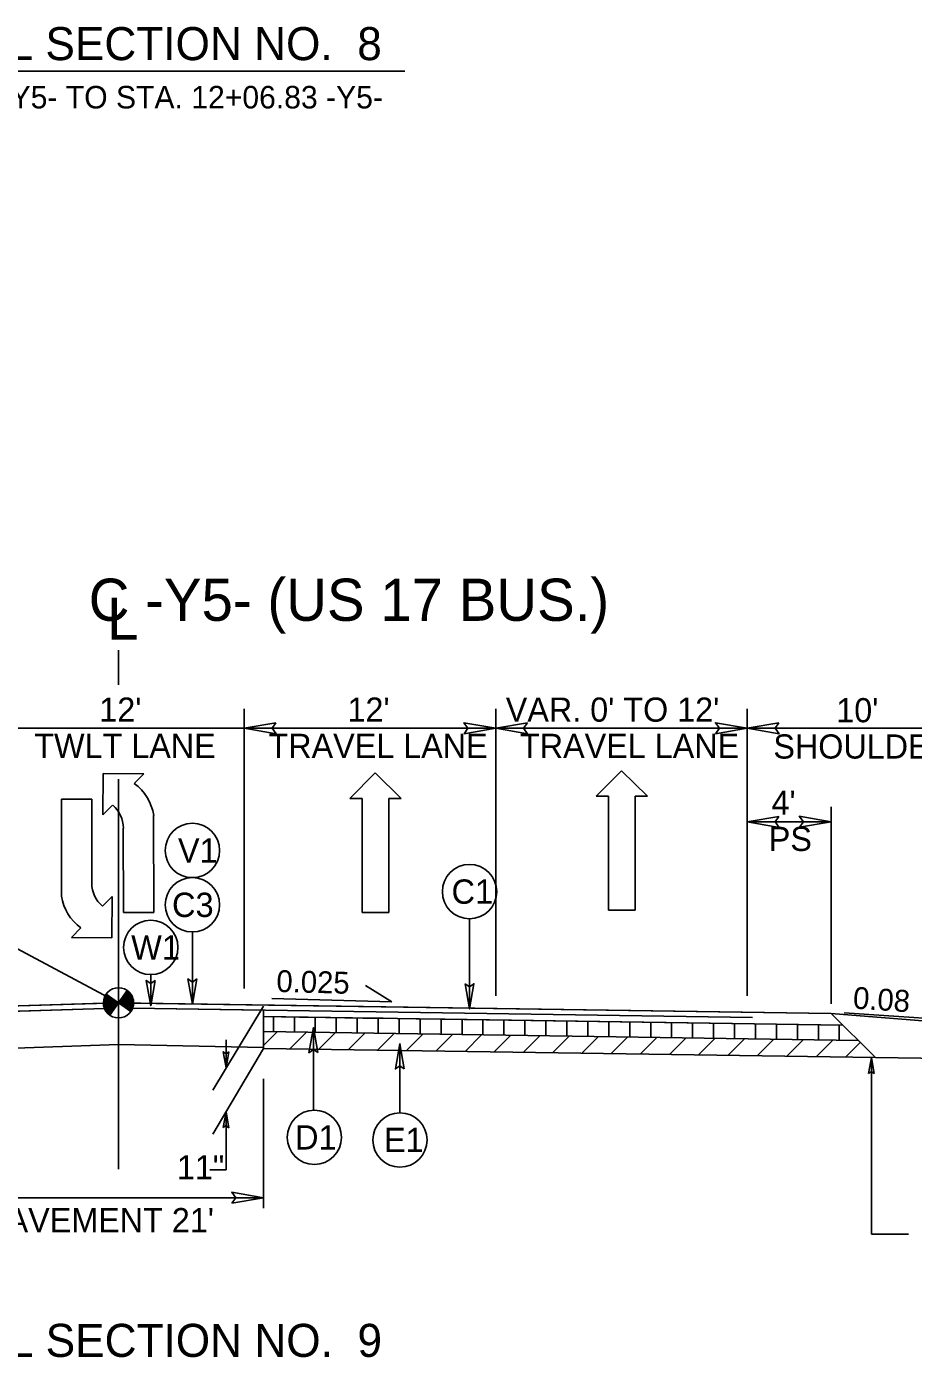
# Model space of a CAD drawing. Extents: x 2176156 to 2177167, y 76401 to 76644.
# Drawn here: x 2176792.8 to 2176835.1, y 76511.9 to 76575.4 of the extents above; entities that cross this region are included whole.
import ezdxf

# ---------------------------------------------------------------- set-up
doc = ezdxf.new("R2010")
doc.units = 0
for name, color, linetype in [('Exist Building', 7, 'Continuous'), ('Exist Building Metal Canopy', 7, 'Continuous'), ('Exist Roads Change in Surface', 7, 'Continuous'), ('Exist Roads Curbs', 7, 'Continuous'), ('Exist Roads EOP Other', 7, 'Continuous'), ('Exist Roads Soil', 7, 'Continuous'), ('Exist Structure Minor Culvert Topo', 7, 'Continuous'), ('Exist Structure Minor Drop Inlet', 7, 'Continuous'), ('Exist Utilities Other Pole CELL', 7, 'Continuous'), ('Exist Vegetation Tree CELL', 7, 'Continuous'), ('Exist Vegetation Woods Line', 7, 'Continuous'), ('Model Boundary Lines Text', 7, 'Continuous'), ('Old_Level_1', 7, 'Continuous'), ('Old_Level_3', 7, 'Continuous'), ('Prop North Arrow NAD83 for Plan Sheets CELL', 7, 'Continuous'), ('Sheet Plan CELL', 7, 'Continuous')]:
    doc.layers.add(name, color=color, linetype=linetype)

msp = doc.modelspace()

# ---------------------------------------------------------------- linework, layer by layer
at = {"layer": 'Exist Building'}
for p, q in [((2176804.065, 76526.664), (2176804.065, 76528.486)), ((2176848.249, 76526.006), (2176804.065, 76526.664))]:
    msp.add_line(p, q, dxfattribs=at)
at = {"layer": 'Exist Roads Change in Surface'}
for p, q in [((2176797.558, 76529.431), (2176797.146, 76528.839)), ((2176797.146, 76528.839), (2176796.554, 76529.251)), ((2176796.734, 76528.247), (2176797.146, 76528.839)), ((2176797.738, 76528.428), (2176797.146, 76528.839)), ((2176797.146, 76528.839), (2176797.738, 76528.428))]:
    msp.add_line(p, q, dxfattribs=at)
for points in [[(2176797.531, 76529.392), (2176797.743, 76529.245)], [(2176797.539, 76529.404), (2176797.715, 76529.282)], [(2176797.548, 76529.416), (2176797.682, 76529.323)], [(2176797.556, 76529.428), (2176797.62, 76529.383)], [(2176796.425, 76528.858), (2176796.92, 76528.514)], [(2176796.425, 76528.841), (2176796.912, 76528.502)], [(2176796.426, 76528.876), (2176796.928, 76528.526)], [(2176796.426, 76528.823), (2176796.903, 76528.49)], [(2176796.426, 76528.805), (2176796.895, 76528.479)], [(2176796.427, 76528.892), (2176796.936, 76528.538)], [(2176796.427, 76528.787), (2176796.887, 76528.467)], [(2176796.429, 76528.908), (2176796.945, 76528.55)], [(2176796.429, 76528.768), (2176796.879, 76528.455)], [(2176796.431, 76528.925), (2176796.953, 76528.561)], [(2176796.432, 76528.941), (2176796.961, 76528.573)], [(2176796.435, 76528.957), (2176796.969, 76528.585)], [(2176796.438, 76528.972), (2176796.977, 76528.597)], [(2176796.441, 76528.988), (2176796.986, 76528.609)], [(2176796.444, 76529.003), (2176796.994, 76528.621)], [(2176796.447, 76529.019), (2176797.002, 76528.632)], [(2176796.452, 76529.033), (2176797.01, 76528.644)], [(2176796.456, 76529.048), (2176797.019, 76528.656)], [(2176796.46, 76529.062), (2176797.027, 76528.668)], [(2176796.466, 76529.076), (2176797.035, 76528.68)], [(2176796.47, 76529.091), (2176797.043, 76528.692)], [(2176796.476, 76529.104), (2176797.052, 76528.703)], [(2176796.481, 76529.118), (2176797.06, 76528.715)], [(2176796.487, 76529.132), (2176797.068, 76528.727)], [(2176796.492, 76529.145), (2176797.076, 76528.739)], [(2176796.499, 76529.158), (2176797.084, 76528.751)], [(2176796.506, 76529.171), (2176797.093, 76528.763)], [(2176796.513, 76529.183), (2176797.101, 76528.774)], [(2176796.52, 76529.196), (2176797.109, 76528.786)], [(2176796.527, 76529.209), (2176797.117, 76528.798)], [(2176796.535, 76529.221), (2176797.126, 76528.81)], [(2176796.542, 76529.234), (2176797.134, 76528.822)], [(2176796.55, 76529.245), (2176796.55, 76529.245), (2176797.142, 76528.834)], [(2176797.152, 76528.848), (2176797.744, 76528.436), (2176797.744, 76528.436)], [(2176797.16, 76528.86), (2176797.752, 76528.448)], [(2176797.169, 76528.872), (2176797.759, 76528.461)], [(2176797.177, 76528.884), (2176797.767, 76528.473)], [(2176797.185, 76528.895), (2176797.774, 76528.486)], [(2176797.193, 76528.907), (2176797.781, 76528.498)], [(2176797.202, 76528.919), (2176797.788, 76528.511)], [(2176797.21, 76528.931), (2176797.794, 76528.525)], [(2176797.218, 76528.943), (2176797.801, 76528.537)], [(2176797.226, 76528.955), (2176797.806, 76528.551)], [(2176797.235, 76528.966), (2176797.812, 76528.565)], [(2176797.243, 76528.978), (2176797.817, 76528.578)], [(2176797.251, 76528.99), (2176797.823, 76528.592)], [(2176797.259, 76529.002), (2176797.827, 76528.607)], [(2176797.267, 76529.014), (2176797.833, 76528.62)], [(2176797.276, 76529.026), (2176797.837, 76528.635)], [(2176797.284, 76529.037), (2176797.841, 76528.649)], [(2176797.292, 76529.049), (2176797.846, 76528.664)], [(2176797.3, 76529.061), (2176797.849, 76528.68)], [(2176797.309, 76529.073), (2176797.852, 76528.695)], [(2176797.317, 76529.085), (2176797.855, 76528.71)], [(2176797.325, 76529.097), (2176797.858, 76528.726)], [(2176797.333, 76529.108), (2176797.861, 76528.741)], [(2176797.342, 76529.12), (2176797.862, 76528.758)], [(2176797.35, 76529.132), (2176797.864, 76528.774)], [(2176797.358, 76529.144), (2176797.866, 76528.791)], [(2176797.366, 76529.156), (2176797.866, 76528.808)], [(2176797.375, 76529.168), (2176797.866, 76528.825)], [(2176797.383, 76529.179), (2176797.867, 76528.843)], [(2176797.391, 76529.191), (2176797.867, 76528.86)], [(2176797.399, 76529.203), (2176797.866, 76528.878)], [(2176797.407, 76529.215), (2176797.865, 76528.897)], [(2176797.416, 76529.227), (2176797.863, 76528.916)], [(2176797.424, 76529.239), (2176797.86, 76528.935)], [(2176797.432, 76529.25), (2176797.858, 76528.954)], [(2176797.44, 76529.262), (2176797.855, 76528.974)], [(2176797.449, 76529.274), (2176797.85, 76528.995)], [(2176797.457, 76529.286), (2176797.845, 76529.016)], [(2176797.465, 76529.298), (2176797.839, 76529.038)], [(2176797.473, 76529.31), (2176797.832, 76529.06)], [(2176797.482, 76529.321), (2176797.825, 76529.083)], [(2176797.49, 76529.333), (2176797.816, 76529.106)], [(2176797.498, 76529.345), (2176797.806, 76529.131)], [(2176797.506, 76529.357), (2176797.793, 76529.157)], [(2176797.515, 76529.369), (2176797.779, 76529.185)], [(2176797.523, 76529.381), (2176797.762, 76529.214)], [(2176796.431, 76528.749), (2176796.87, 76528.443)], [(2176796.434, 76528.73), (2176796.862, 76528.431)], [(2176796.437, 76528.71), (2176796.854, 76528.419)], [(2176796.441, 76528.689), (2176796.846, 76528.408)], [(2176796.446, 76528.668), (2176796.837, 76528.396)], [(2176796.452, 76528.647), (2176796.829, 76528.384)], [(2176796.458, 76528.625), (2176796.821, 76528.372)], [(2176796.466, 76528.602), (2176796.813, 76528.36)], [(2176796.474, 76528.578), (2176796.804, 76528.348)], [(2176796.485, 76528.553), (2176796.796, 76528.337)], [(2176796.496, 76528.528), (2176796.788, 76528.325)], [(2176796.509, 76528.501), (2176796.78, 76528.313)], [(2176796.526, 76528.472), (2176796.772, 76528.301)], [(2176796.545, 76528.441), (2176796.763, 76528.289)], [(2176796.57, 76528.406), (2176796.755, 76528.277)], [(2176796.602, 76528.366), (2176796.747, 76528.266)], [(2176796.654, 76528.312), (2176796.739, 76528.254)]]:
    msp.add_lwpolyline(points, dxfattribs=at)
msp.add_circle((2176797.146, 76528.84), 0.721, dxfattribs=at)
for start, end in [(325.1751, 55.1751), (145.1751, 235.1751)]:
    msp.add_arc((2176797.146, 76528.84), 0.721, start, end, dxfattribs=at)
at = {"layer": 'Exist Roads Curbs'}
for p, q in [((2176797.146, 76528.839), (2176763.146, 76527.778)), ((2176797.146, 76528.839), (2176831.146, 76528.334)), ((2176796.478, 76528.568), (2176762.886, 76527.52)), ((2176797.818, 76528.579), (2176827.401, 76528.139))]:
    msp.add_line(p, q, dxfattribs=at)
at = {"layer": 'Exist Roads EOP Other'}
for p, q in [((2176796.426, 76528.816), (2176763.146, 76527.778)), ((2176796.426, 76528.805), (2176796.426, 76528.805)), ((2176796.427, 76528.787), (2176796.427, 76528.787)), ((2176797.865, 76528.791), (2176797.866, 76528.791)), ((2176831.146, 76528.334), (2176797.867, 76528.828)), ((2176796.434, 76528.729), (2176796.434, 76528.73)), ((2176796.437, 76528.71), (2176796.437, 76528.71)), ((2176796.441, 76528.689), (2176796.441, 76528.689)), ((2176796.446, 76528.668), (2176796.446, 76528.668)), ((2176796.458, 76528.625), (2176796.458, 76528.625)), ((2176796.466, 76528.602), (2176796.466, 76528.602)), ((2176797.833, 76528.62), (2176797.833, 76528.62)), ((2176797.841, 76528.649), (2176797.841, 76528.649)), ((2176797.845, 76528.664), (2176797.846, 76528.664)), ((2176797.86, 76528.742), (2176797.861, 76528.741)), ((2176831.146, 76528.334), (2176837.181, 76527.851)), ((2176831.708, 76527.774), (2176831.146, 76528.334)), ((2176812.737, 76528.055), (2176831.708, 76527.774))]:
    msp.add_line(p, q, dxfattribs=at)
for points in [[(2176796.426, 76528.805), (2176796.426, 76528.805)], [(2176796.427, 76528.787), (2176796.427, 76528.787)], [(2176797.866, 76528.791), (2176797.865, 76528.791)], [(2176773.445, 76527.464), (2176774.959, 76527.487), (2176776.433, 76527.509), (2176777.013, 76527.517), (2176777.705, 76527.527), (2176778.76, 76527.543), (2176780.289, 76527.566), (2176780.289, 76528.063), (2176796.478, 76528.568)], [(2176796.434, 76528.73), (2176796.434, 76528.73)], [(2176796.437, 76528.71), (2176796.437, 76528.71)], [(2176796.441, 76528.689), (2176796.441, 76528.69)], [(2176796.446, 76528.668), (2176796.446, 76528.669)], [(2176796.458, 76528.625), (2176796.458, 76528.625)], [(2176796.466, 76528.602), (2176796.466, 76528.602)], [(2176797.818, 76528.579), (2176804.065, 76528.486), (2176804.065, 76528.186), (2176805.775, 76528.16), (2176807.023, 76528.142), (2176807.947, 76528.128), (2176808.797, 76528.115), (2176809.773, 76528.101), (2176810.454, 76528.091), (2176811.35, 76528.077), (2176812.737, 76528.055)], [(2176797.833, 76528.62), (2176797.833, 76528.62)], [(2176797.841, 76528.649), (2176797.841, 76528.649)], [(2176797.846, 76528.664), (2176797.845, 76528.664)], [(2176797.861, 76528.741), (2176797.86, 76528.742)]]:
    msp.add_lwpolyline(points, dxfattribs=at)
for start, end in [(181.84773, 182.73482), (182.76061, 184.18733), (184.2222, 187.24612), (352.19059, 353.48791), (353.48791, 354.79788), (354.79788, 356.11053), (356.1239, 357.48537), (357.48537, 358.86532), (358.86532, 359.08637), (187.24612, 188.78039), (188.79621, 190.40163), (190.40198, 192.0225), (192.05448, 193.73519), (193.75955, 195.5443), (195.5443, 197.35402), (197.35715, 199.26319), (199.26898, 202.1386), (338.78738, 342.28458), (342.2873, 344.70243), (344.70321, 345.9093), (345.92456, 349.66638), (349.66638, 350.92326), (350.92326, 352.17553)]:
    msp.add_arc((2176797.146, 76528.84), 0.721, start, end, dxfattribs=at)
at = {"layer": 'Exist Roads Soil'}
for p, q in [((2176804.065, 76528.186), (2176831.708, 76527.774)), ((2176831.146, 76528.334), (2176833.262, 76526.229)), ((2176804.077, 76527.47), (2176832.439, 76527.048))]:
    msp.add_line(p, q, dxfattribs=at)
at = {"layer": 'Exist Structure Minor Drop Inlet'}
for p, q in [((2176808.19, 76538.584), (2176809.393, 76539.807)), ((2176809.393, 76539.807), (2176810.634, 76538.584)), ((2176819.943, 76538.689), (2176821.146, 76539.912)), ((2176821.146, 76539.912), (2176822.387, 76538.689)), ((2176808.772, 76538.584), (2176808.19, 76538.584)), ((2176808.772, 76533.152), (2176808.772, 76538.584)), ((2176810.634, 76538.584), (2176810.052, 76538.584)), ((2176810.052, 76538.584), (2176810.052, 76533.152)), ((2176820.525, 76538.689), (2176819.943, 76538.689)), ((2176820.525, 76533.257), (2176820.525, 76538.689)), ((2176822.387, 76538.689), (2176821.805, 76538.689)), ((2176821.805, 76538.689), (2176821.805, 76533.257)), ((2176821.805, 76533.257), (2176820.525, 76533.257)), ((2176810.052, 76533.152), (2176808.772, 76533.152))]:
    msp.add_line(p, q, dxfattribs=at)
at = {"layer": 'Exist Utilities Other Pole CELL'}
for p, q in [((2176810.195, 76528.894), (2176808.939, 76529.664)), ((2176810.195, 76528.894), (2176804.47, 76529.043)), ((2176836.517, 76528.045), (2176831.771, 76528.358))]:
    msp.add_line(p, q, dxfattribs=at)
at = {"layer": 'Exist Vegetation Tree CELL'}
for p, q in [((2176796.422, 76539.774), (2176796.404, 76537.799)), ((2176798.353, 76539.755), (2176796.422, 76539.774)), ((2176797.893, 76539.294), (2176798.353, 76539.755)), ((2176795.872, 76538.561), (2176794.424, 76538.559)), ((2176794.424, 76538.559), (2176794.432, 76533.929)), ((2176795.879, 76534.546), (2176795.872, 76538.561)), ((2176796.404, 76537.799), (2176796.864, 76538.261)), ((2176798.826, 76533.152), (2176798.817, 76537.782)), ((2176797.37, 76537.165), (2176797.378, 76533.15)), ((2176796.846, 76533.912), (2176796.386, 76533.45)), ((2176796.827, 76531.937), (2176796.846, 76533.912)), ((2176797.378, 76533.15), (2176798.826, 76533.152)), ((2176795.356, 76532.417), (2176794.897, 76531.956)), ((2176794.897, 76531.956), (2176796.827, 76531.937))]:
    msp.add_line(p, q, dxfattribs=at)
for centre, radius, start, end in [((2176796.547, 76537.43), 2.305, 8.7824, 54.0941), ((2176795.941, 76537.167), 1.437, 0.10633, 49.76451), ((2176797.309, 76534.544), 1.437, 180.10633, 229.76451), ((2176796.702, 76534.281), 2.305, 188.7824, 234.0941)]:
    msp.add_arc(centre, radius, start, end, dxfattribs=at)
at = {"layer": 'Model Boundary Lines Text'}
for p, q in [((2176783.485, 76573.271), (2176810.807, 76573.271)), ((2176804.537, 76527.463), (2176804.537, 76528.179)), ((2176805.537, 76527.448), (2176805.537, 76528.164)), ((2176806.537, 76527.433), (2176806.537, 76528.149)), ((2176807.537, 76527.418), (2176807.537, 76528.134)), ((2176808.537, 76527.403), (2176808.537, 76528.119)), ((2176809.537, 76527.389), (2176809.537, 76528.104)), ((2176810.537, 76527.374), (2176810.537, 76528.089)), ((2176811.537, 76527.359), (2176811.537, 76528.074)), ((2176812.537, 76527.344), (2176812.537, 76528.06)), ((2176813.537, 76527.329), (2176813.537, 76528.045)), ((2176814.537, 76527.314), (2176814.537, 76528.03)), ((2176815.537, 76527.299), (2176815.537, 76528.015)), ((2176816.537, 76527.284), (2176816.537, 76528)), ((2176817.537, 76527.269), (2176817.537, 76527.985)), ((2176818.537, 76527.255), (2176818.537, 76527.97)), ((2176819.537, 76527.24), (2176819.537, 76527.955)), ((2176820.537, 76527.225), (2176820.537, 76527.941)), ((2176821.537, 76527.21), (2176821.537, 76527.926)), ((2176822.537, 76527.195), (2176822.537, 76527.911)), ((2176823.537, 76527.18), (2176823.537, 76527.896)), ((2176824.537, 76527.165), (2176824.537, 76527.881)), ((2176825.537, 76527.15), (2176825.537, 76527.866)), ((2176826.537, 76527.135), (2176826.537, 76527.851)), ((2176827.537, 76527.121), (2176827.537, 76527.836)), ((2176828.538, 76527.106), (2176828.538, 76527.821)), ((2176829.538, 76527.091), (2176829.538, 76527.807)), ((2176830.538, 76527.076), (2176830.538, 76527.792)), ((2176831.538, 76527.061), (2176831.538, 76527.777)), ((2176804.065, 76526.807), (2176804.719, 76527.46)), ((2176805.318, 76526.645), (2176806.113, 76527.439)), ((2176806.711, 76526.624), (2176807.506, 76527.419)), ((2176808.105, 76526.603), (2176808.899, 76527.398)), ((2176809.498, 76526.583), (2176810.293, 76527.377)), ((2176810.892, 76526.562), (2176811.686, 76527.357)), ((2176812.285, 76526.541), (2176813.08, 76527.336)), ((2176813.679, 76526.521), (2176814.473, 76527.315)), ((2176815.072, 76526.5), (2176815.867, 76527.294)), ((2176816.466, 76526.479), (2176817.26, 76527.274)), ((2176817.859, 76526.458), (2176818.654, 76527.253)), ((2176819.253, 76526.438), (2176820.047, 76527.232)), ((2176820.646, 76526.417), (2176821.441, 76527.211)), ((2176822.04, 76526.396), (2176822.834, 76527.191)), ((2176823.433, 76526.375), (2176824.228, 76527.17)), ((2176824.827, 76526.355), (2176825.621, 76527.149)), ((2176826.22, 76526.334), (2176827.015, 76527.128)), ((2176827.614, 76526.313), (2176828.408, 76527.108)), ((2176829.041, 76526.292), (2176829.835, 76527.086)), ((2176830.434, 76526.271), (2176831.228, 76527.066)), ((2176831.828, 76526.25), (2176832.535, 76526.952))]:
    msp.add_line(p, q, dxfattribs=at)
at = {"layer": 'Old_Level_1'}
for points in [[(2176804.655, 76542.192), (2176803.146, 76541.932), (2176804.664, 76541.663), (2176804.471, 76541.932)], [(2176813.636, 76541.672), (2176815.146, 76541.932), (2176813.628, 76542.2), (2176813.821, 76541.932)], [(2176816.655, 76542.192), (2176815.146, 76541.932), (2176816.664, 76541.663), (2176816.471, 76541.932)], [(2176825.636, 76541.672), (2176827.146, 76541.932), (2176825.628, 76542.2), (2176825.821, 76541.932)], [(2176828.655, 76542.192), (2176827.146, 76541.932), (2176828.664, 76541.663), (2176828.471, 76541.932)], [(2176828.655, 76537.731), (2176827.146, 76537.471), (2176828.664, 76537.203), (2176828.471, 76537.471)], [(2176829.636, 76537.211), (2176831.146, 76537.471), (2176829.628, 76537.74), (2176829.821, 76537.471)], [(2176802.41, 76526.501), (2176802.278, 76525.747), (2176802.146, 76526.506), (2176802.28, 76526.409)], [(2176832.936, 76525.477), (2176833.066, 76526.232), (2176833.2, 76525.473), (2176833.066, 76525.57)], [(2176802.145, 76522.89), (2176802.277, 76523.645), (2176802.409, 76522.885), (2176802.275, 76522.982)], [(2176802.558, 76519.28), (2176804.068, 76519.54), (2176802.55, 76519.808), (2176802.743, 76519.54)]]:
    msp.add_lwpolyline(points, close=True, dxfattribs=at)
at = {"layer": 'Old_Level_3'}
for p, q in [((2176797.146, 76544.011), (2176797.146, 76545.663)), ((2176803.146, 76529.531), (2176803.146, 76542.859)), ((2176815.146, 76529.172), (2176815.146, 76542.859)), ((2176827.146, 76529.172), (2176827.146, 76542.859)), ((2176729.146, 76541.932), (2176797.172, 76541.932)), ((2176797.172, 76541.932), (2176865.133, 76541.932)), ((2176797.146, 76520.9), (2176797.146, 76539.505)), ((2176831.146, 76529.106), (2176831.146, 76538.181)), ((2176831.146, 76528.799), (2176831.146, 76538.181)), ((2176827.146, 76537.471), (2176831.146, 76537.471)), ((2176804.066, 76528.679), (2176801.641, 76524.671)), ((2176802.278, 76525.747), (2176802.278, 76527.075)), ((2176804.065, 76526.664), (2176801.64, 76522.57)), ((2176833.066, 76526.232), (2176833.066, 76517.807)), ((2176804.068, 76525.212), (2176804.068, 76519.049)), ((2176802.277, 76520.869), (2176802.277, 76523.645)), ((2176801.497, 76520.869), (2176802.277, 76520.869)), ((2176804.068, 76519.54), (2176780.289, 76519.54)), ((2176834.832, 76517.807), (2176833.066, 76517.807))]:
    msp.add_line(p, q, dxfattribs=at)
at = {"layer": 'Prop North Arrow NAD83 for Plan Sheets CELL'}
for p, q in [((2176813.894, 76532.849), (2176813.894, 76528.546)), ((2176800.675, 76532.218), (2176800.675, 76528.777)), ((2176791.82, 76531.691), (2176797.146, 76528.839)), ((2176798.687, 76530.185), (2176798.687, 76528.702)), ((2176806.445, 76523.718), (2176806.445, 76527.663)), ((2176810.575, 76523.595), (2176810.575, 76526.891))]:
    msp.add_line(p, q, dxfattribs=at)
for points in [[(2176798.894, 76529.902), (2176798.687, 76528.702), (2176798.474, 76529.909), (2176798.687, 76529.756)], [(2176800.882, 76529.977), (2176800.675, 76528.777), (2176800.462, 76529.984), (2176800.675, 76529.83)], [(2176813.687, 76529.746), (2176813.894, 76528.546), (2176814.107, 76529.753), (2176813.894, 76529.6)], [(2176806.652, 76526.463), (2176806.445, 76527.663), (2176806.232, 76526.456), (2176806.445, 76526.609)], [(2176810.782, 76525.691), (2176810.575, 76526.891), (2176810.362, 76525.684), (2176810.575, 76525.838)]]:
    msp.add_lwpolyline(points, close=True, dxfattribs=at)
for centre in [(2176800.675, 76536.106), (2176813.894, 76534.145), (2176800.675, 76533.514), (2176798.687, 76531.481), (2176806.492, 76522.423), (2176810.575, 76522.299)]:
    msp.add_circle(centre, 1.296, dxfattribs=at)
at = {"layer": 'Sheet Plan CELL'}
for p in [(2176780.289, 76526.248), (2176804.065, 76526.716)]:
    msp.add_line(p, (2176797.146, 76526.859), dxfattribs=at)

# ---------------------------------------------------------------- texts
at = {"layer": 'Exist Building Metal Canopy'}
for s, p in [('TYPICAL SECTION NO.  8', (2176784.288, 76573.8)), ('TYPICAL SECTION NO.  9', (2176784.299, 76511.952))]:
    msp.add_text(s, height=1.5766, rotation=0.00002, dxfattribs=at).set_placement(p)
at = {"layer": 'Exist Structure Minor Culvert Topo'}
for s, height, p in [("12'", 1.1533, (2176796.232, 76542.248)), ("12'", 1.1533, (2176808.073, 76542.248)), ("VAR. 0' TO 12'", 1.15334, (2176815.624, 76542.248)), ("10' ", 1.1533, (2176831.392, 76542.22)), ('TWLT LANE', 1.1533, (2176793.131, 76540.518)), ('TRAVEL LANE', 1.15334, (2176804.303, 76540.518)), ('TRAVEL LANE', 1.15334, (2176816.303, 76540.518)), ('SHOULDER', 1.1533, (2176828.391, 76540.49)), ("4' ", 1.1533, (2176828.302, 76537.813)), ('PS', 1.1533, (2176828.172, 76536.083)), ("EXIST. PAVEMENT 21'", 1.15334, (2176785.466, 76517.899))]:
    msp.add_text(s, height=height, dxfattribs=at).set_placement(p)
at = {"layer": 'Exist Utilities Other Pole CELL'}
for s, rotation, p in [('0.025', 358.50681, (2176804.671, 76529.36)), ('0.08', 356.21988, (2176832.167, 76528.569))]:
    msp.add_text(s, height=1.0429, rotation=rotation, dxfattribs=at).set_placement(p)
at = {"layer": 'Exist Vegetation Woods Line'}
for s, height, p in [('STA. 10+54.20 -Y5- TO STA. 12+06.83 -Y5-', 1.0742, (2176781.498, 76571.497)), ('C -Y5- (US 17 BUS.) ', 2.01314, (2176795.725, 76547.058))]:
    msp.add_text(s, height=height, dxfattribs=at).set_placement(p)
msp.add_text('L', height=2.013, rotation=359.9469, dxfattribs=at).set_placement((2176796.603, 76546.156))
at = {"layer": 'Prop North Arrow NAD83 for Plan Sheets CELL'}
for s, rotation, p in [('V1', 0.00026, (2176799.982, 76535.526)), ('C1', 359.99974, (2176813.037, 76533.565)), ('C3', 0.00026, (2176799.702, 76532.934)), ('W1', 0.00026, (2176797.75, 76530.901)), ('D1', 359.99974, (2176805.571, 76521.843)), ('E1', 359.99974, (2176809.811, 76521.719))]:
    msp.add_text(s, height=1.16, rotation=rotation, dxfattribs=at).set_placement(p)
msp.add_text('11"', height=1.1533, dxfattribs=at).set_placement((2176799.932, 76520.419))

doc.saveas('drawing.dxf')
